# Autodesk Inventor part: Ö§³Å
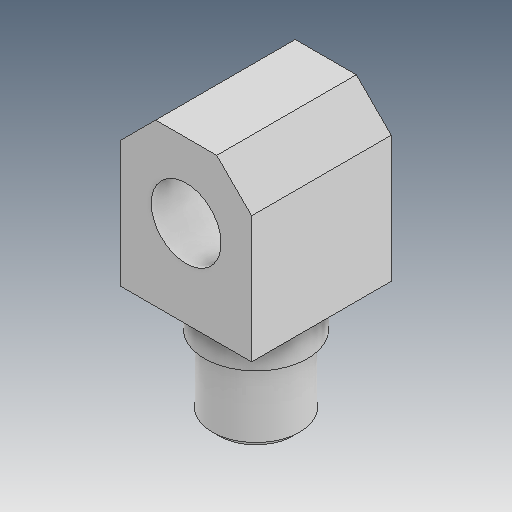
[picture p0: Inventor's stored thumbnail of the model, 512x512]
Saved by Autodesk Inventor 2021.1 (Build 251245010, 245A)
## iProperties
Created: 2019-04
Part Number: Ö§³Å
Material: Ogólny
Document SubType Name: Modeling
Designer: user
Density: 1 g/cm^3
Appearance: Domyślna
Author: user
Revision Number: ÈÎºÎ
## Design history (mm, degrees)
feature "ÊäÈë1"
node "Bryła1"
